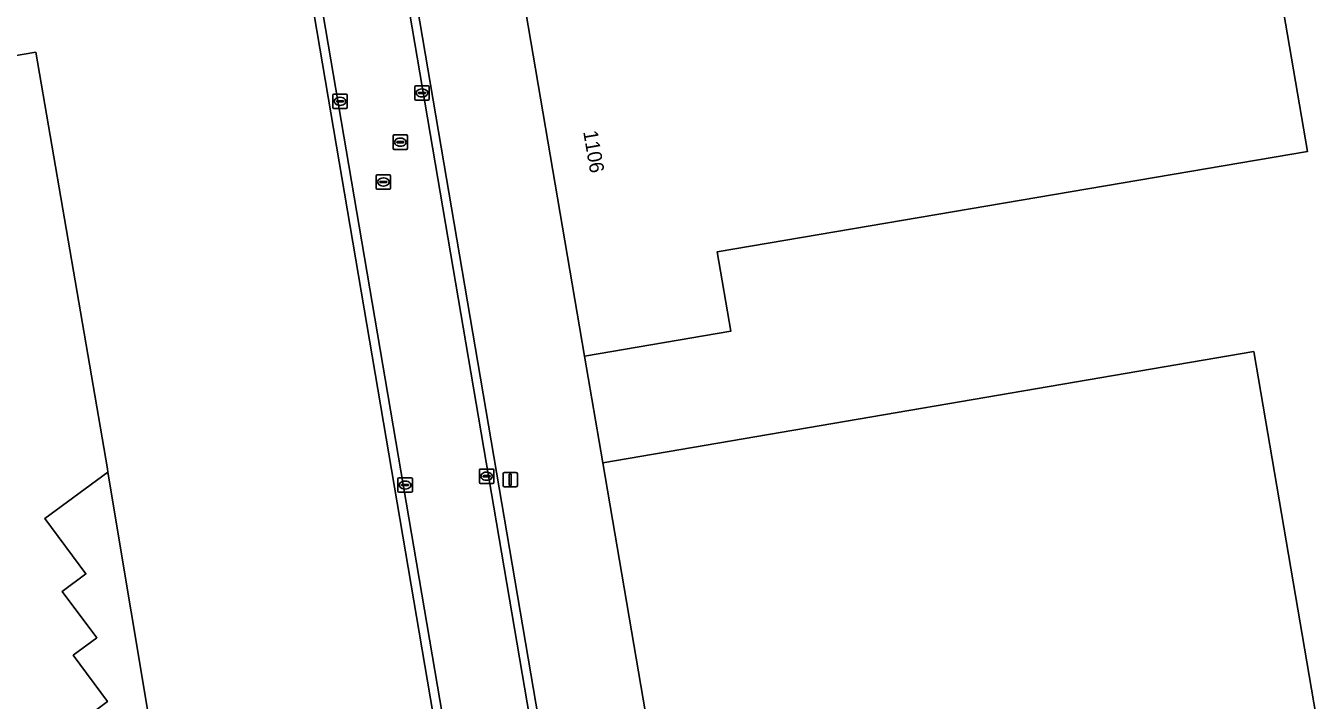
# Model space of a CAD drawing. Extents: x 154324 to 155744, y 382937 to 384188.
# Drawn here: x 154922.2 to 155011.6, y 383247.7 to 383294.5 of the extents above; entities that cross this region are included whole.
import ezdxf

# ---------------------------------------------------------------- set-up
doc = ezdxf.new("R2010")
doc.units = 0
for name, color, linetype in [('IMGEO_Erf', 7, 'Continuous'), ('IMGEO_Kolk', 7, 'Continuous'), ('IMGEO_Lichtmast', 7, 'Continuous'), ('IMGEO_Pand', 7, 'Continuous'), ('IMGEO_Pand_nummerreeks', 7, 'Continuous'), ('IMGEO_Pand_overbouw', 7, 'Continuous'), ('IMGEO_Parkeervlak_open', 7, 'Continuous'), ('IMGEO_Rijbaan_lokaal_gesloten', 7, 'Continuous'), ('IMGEO_Rijbaan_lokaal_open', 7, 'Continuous'), ('IMGEO_Rioolput', 7, 'Continuous')]:
    doc.layers.add(name, color=color, linetype=linetype)

msp = doc.modelspace()

# ---------------------------------------------------------------- linework, layer by layer
at = {"layer": 'IMGEO_Erf'}
for points in [[(154957.636, 383205.007), (154955.126, 383219.621), (154933.063, 383349.385), (154931.446, 383358.867), (154880.326, 383658.587)], [(155062.526, 383340.029), (155003.646, 383330.283), (155005.673, 383318.494), (154961.037, 383310.872), (154960.776, 383312.399), (154955.689, 383311.55), (154954.834, 383316.483), (154953.74, 383316.294), (154953.892, 383315.524), (154953.555, 383315.462), (154954.479, 383309.839), (154956.449, 383298.428), (154958.963, 383298.857), (154958.072, 383304.074), (155006.663, 383312.344), (155011.213, 383285.747), (154970.24, 383278.793), (154971.18, 383273.272), (154961.04, 383271.548), (154962.295, 383264.145), (155007.491, 383271.866), (155014.059, 383233.409)], [(154854.938, 383281.039), (154922.938, 383292.639), (154927.907, 383263.724), (154927.942, 383263.507), (154923.572, 383260.288), (154926.413, 383256.439), (154924.778, 383255.22), (154927.17, 383252.008), (154925.538, 383250.794), (154927.916, 383247.585), (154926.283, 383246.367), (154929.131, 383242.58), (154931.183, 383244.108), (154931.296, 383243.969), (154938.169, 383203.279), (154923.048, 383200.725), (154925.906, 383183.809), (154890.471, 383163.81)]]:
    msp.add_lwpolyline(points, dxfattribs=at)
at = {"layer": 'IMGEO_Kolk'}
for p, q in [((154949.247, 383289.386), (154949.247, 383290.238)), ((154949.322, 383290.312), (154950.174, 383290.312)), ((154949.735, 383290.092), (154949.76, 383290.092)), ((154950.248, 383290.238), (154950.248, 383289.386)), ((154943.56, 383288.804), (154943.56, 383289.656)), ((154943.635, 383289.73), (154944.487, 383289.73)), ((154943.819, 383289.224), (154943.819, 383289.236)), ((154944.257, 383289.187), (154943.859, 383289.187)), ((154943.862, 383289.273), (154944.26, 383289.273)), ((154944.048, 383289.51), (154944.073, 383289.51)), ((154944.303, 383289.236), (154944.303, 383289.224)), ((154944.561, 383289.656), (154944.561, 383288.804)), ((154950.174, 383289.312), (154949.322, 383289.312)), ((154949.506, 383289.806), (154949.506, 383289.818)), ((154949.944, 383289.769), (154949.546, 383289.769)), ((154949.549, 383289.855), (154949.947, 383289.855)), ((154949.758, 383289.532), (154949.733, 383289.532)), ((154949.99, 383289.818), (154949.99, 383289.806)), ((154944.487, 383288.73), (154943.635, 383288.73)), ((154944.071, 383288.95), (154944.046, 383288.95)), ((154948.153, 383263.106), (154949.005, 383263.106)), ((154953.734, 383262.792), (154953.734, 383263.644)), ((154953.809, 383263.718), (154954.661, 383263.718)), ((154953.993, 383263.212), (154953.993, 383263.224)), ((154954.431, 383263.175), (154954.033, 383263.175)), ((154954.036, 383263.261), (154954.434, 383263.261)), ((154954.222, 383263.498), (154954.247, 383263.498)), ((154954.477, 383263.224), (154954.477, 383263.212)), ((154954.735, 383263.644), (154954.735, 383262.792)), ((154948.078, 383262.18), (154948.078, 383263.032)), ((154948.337, 383262.6), (154948.337, 383262.612)), ((154948.775, 383262.563), (154948.377, 383262.563)), ((154948.38, 383262.649), (154948.778, 383262.649)), ((154948.589, 383262.326), (154948.564, 383262.326)), ((154948.566, 383262.886), (154948.591, 383262.886)), ((154948.821, 383262.612), (154948.821, 383262.6)), ((154949.079, 383263.032), (154949.079, 383262.18)), ((154954.661, 383262.718), (154953.809, 383262.718)), ((154954.245, 383262.938), (154954.22, 383262.938)), ((154949.005, 383262.106), (154948.153, 383262.106))]:
    msp.add_line(p, q, dxfattribs=at)
for points in [[(154949.247, 383289.386), (154949.247, 383290.238)], [(154949.322, 383290.312), (154950.174, 383290.312)], [(154950.248, 383290.238), (154950.248, 383289.386)], [(154943.56, 383288.804), (154943.56, 383289.656)], [(154943.635, 383289.73), (154944.487, 383289.73)], [(154944.561, 383289.656), (154944.561, 383288.804)], [(154950.174, 383289.312), (154949.322, 383289.312)], [(154944.487, 383288.73), (154943.635, 383288.73)], [(154948.153, 383263.106), (154949.005, 383263.106)], [(154953.734, 383262.792), (154953.734, 383263.644)], [(154953.809, 383263.718), (154954.661, 383263.718)], [(154954.735, 383263.644), (154954.735, 383262.792)], [(154948.078, 383262.18), (154948.078, 383263.032)], [(154949.079, 383263.032), (154949.079, 383262.18)], [(154954.661, 383262.718), (154953.809, 383262.718)], [(154949.005, 383262.106), (154948.153, 383262.106)]]:
    msp.add_lwpolyline(points, dxfattribs=at)
for centre, radius, start, end in [((154949.324, 383290.236), 0.0765, 91.55205, 178.44795), ((154949.324, 383290.236), 0.0765, 91.55205, 178.44795), ((154950.172, 383290.236), 0.0765, 1.55205, 88.44795), ((154950.172, 383290.236), 0.0765, 1.55205, 88.44795), ((154943.637, 383289.654), 0.0765, 91.55205, 178.44795), ((154943.637, 383289.654), 0.0765, 91.55205, 178.44795), ((154943.859, 383289.233), 0.0403, 85.87752, 175.75265), ((154943.856, 383289.223), 0.0366, 178.93798, 274.71019), ((154944.26, 383289.23), 0.043, 264.86636, 352.45326), ((154944.264, 383289.235), 0.0386, 1.73085, 96.63898), ((154944.485, 383289.654), 0.0765, 1.55205, 88.44795), ((154944.485, 383289.654), 0.0765, 1.55205, 88.44795), ((154949.324, 383289.388), 0.0765, 181.55205, 268.44795), ((154949.324, 383289.388), 0.0765, 181.55205, 268.44795), ((154949.546, 383289.815), 0.0403, 85.87752, 175.75265), ((154949.543, 383289.805), 0.0366, 178.93798, 274.71019), ((154949.947, 383289.812), 0.043, 264.86636, 352.45326), ((154949.951, 383289.817), 0.0386, 1.73085, 96.63898), ((154950.172, 383289.388), 0.0765, 271.55205, 358.44795), ((154950.172, 383289.388), 0.0765, 271.55205, 358.44795), ((154943.637, 383288.806), 0.0765, 181.55205, 268.44795), ((154943.637, 383288.806), 0.0765, 181.55205, 268.44795), ((154944.485, 383288.806), 0.0765, 271.55205, 358.44795), ((154944.485, 383288.806), 0.0765, 271.55205, 358.44795), ((154948.155, 383263.03), 0.0765, 91.55205, 178.44795), ((154948.155, 383263.03), 0.0765, 91.55205, 178.44795), ((154949.003, 383263.03), 0.0765, 1.55205, 88.44795), ((154949.003, 383263.03), 0.0765, 1.55205, 88.44795), ((154953.811, 383263.642), 0.0765, 91.55205, 178.44795), ((154953.811, 383263.642), 0.0765, 91.55205, 178.44795), ((154954.033, 383263.221), 0.0403, 85.87752, 175.75265), ((154954.03, 383263.211), 0.0366, 178.93798, 274.71019), ((154954.434, 383263.218), 0.043, 264.86636, 352.45326), ((154954.438, 383263.223), 0.0386, 1.73085, 96.63898), ((154954.659, 383263.642), 0.0765, 1.55205, 88.44795), ((154954.659, 383263.642), 0.0765, 1.55205, 88.44795), ((154948.155, 383262.182), 0.0765, 181.55205, 268.44795), ((154948.155, 383262.182), 0.0765, 181.55205, 268.44795), ((154948.377, 383262.609), 0.0403, 85.87752, 175.75265), ((154948.374, 383262.599), 0.0366, 178.93798, 274.71019), ((154948.778, 383262.606), 0.043, 264.86636, 352.45326), ((154948.782, 383262.611), 0.0386, 1.73085, 96.63898), ((154949.003, 383262.182), 0.0765, 271.55205, 358.44795), ((154949.003, 383262.182), 0.0765, 271.55205, 358.44795), ((154953.811, 383262.794), 0.0765, 181.55205, 268.44795), ((154953.811, 383262.794), 0.0765, 181.55205, 268.44795), ((154954.659, 383262.794), 0.0765, 271.55205, 358.44795), ((154954.659, 383262.794), 0.0765, 271.55205, 358.44795)]:
    msp.add_arc(centre, radius, start, end, dxfattribs=at)
for centre, major_axis, ratio, start_param, end_param in [((154949.734, 383289.812), (-0.387, 0.002), 0.722429, 4.712389, 7.853982), ((154949.759, 383289.812), (-0.39, 0.002), 0.717154, 1.570796, 4.712389), ((154944.047, 383289.23), (-0.387, 0.002), 0.722429, 4.712389, 7.853982), ((154944.072, 383289.23), (-0.39, 0.002), 0.717154, 1.570796, 4.712389), ((154954.221, 383263.218), (-0.387, 0.002), 0.722429, 4.712389, 7.853982), ((154954.246, 383263.218), (-0.39, 0.002), 0.717154, 1.570796, 4.712389), ((154948.565, 383262.606), (-0.387, 0.002), 0.722429, 4.712389, 7.853982), ((154948.59, 383262.606), (-0.39, 0.002), 0.717154, 1.570796, 4.712389)]:
    msp.add_ellipse(centre, major_axis=major_axis, ratio=ratio, start_param=start_param, end_param=end_param, dxfattribs=at)
at = {"layer": 'IMGEO_Lichtmast'}
for p, q in [((154955.378, 383262.577), (154955.378, 383263.377)), ((154955.378, 383263.377), (154955.378, 383262.577)), ((154955.478, 383263.477), (154956.268, 383263.477)), ((154956.268, 383263.477), (154955.478, 383263.477)), ((154956.368, 383263.377), (154956.368, 383262.577)), ((154956.368, 383262.577), (154956.368, 383263.377)), ((154956.268, 383262.477), (154955.478, 383262.477)), ((154955.478, 383262.477), (154956.268, 383262.477))]:
    msp.add_line(p, q, dxfattribs=at)
msp.add_lwpolyline([(154955.798, 383263.352), (154955.948, 383263.352), (154955.948, 383262.602), (154955.798, 383262.602), (154955.798, 383263.352)], dxfattribs=at)
for centre, start, end in [((154955.478, 383263.377), 90, 180), ((154955.478, 383263.377), 90, 180), ((154956.268, 383263.377), 0, 90), ((154956.268, 383263.377), 360, 90), ((154955.478, 383262.577), 180, 270), ((154955.478, 383262.577), 180, 270), ((154956.268, 383262.577), 270, 0), ((154956.268, 383262.577), 270, 0)]:
    msp.add_arc(centre, 0.1, start, end, dxfattribs=at)
at = {"layer": 'IMGEO_Pand'}
msp.add_lwpolyline([(154958.072, 383304.074), (154958.963, 383298.857), (154956.449, 383298.428), (154961.04, 383271.548), (154971.18, 383273.272), (154970.24, 383278.793), (155011.213, 383285.747), (155006.663, 383312.344)], close=True, dxfattribs=at)
for points in [[(154890.471, 383163.81), (154925.906, 383183.809), (154923.048, 383200.725), (154938.169, 383203.279), (154931.296, 383243.969), (154931.183, 383244.108), (154929.131, 383242.58), (154926.283, 383246.367), (154927.916, 383247.585), (154925.538, 383250.794), (154927.17, 383252.008), (154924.778, 383255.22), (154926.413, 383256.439), (154923.572, 383260.288), (154927.942, 383263.507), (154927.907, 383263.724), (154922.938, 383292.639), (154854.938, 383281.039)], [(154979.95, 383215.582), (154981.386, 383216.111), (154981.866, 383215.269), (155014.059, 383233.409), (155007.491, 383271.866), (154962.295, 383264.145), (154969.397, 383222.533), (154970.312, 383222.697), (154970.556, 383221.2)]]:
    msp.add_lwpolyline(points, dxfattribs=at)
at = {"layer": 'IMGEO_Pand_overbouw'}
msp.add_lwpolyline([(154931.183, 383244.108), (154927.942, 383263.507), (154923.572, 383260.288), (154926.413, 383256.439), (154924.778, 383255.22), (154927.17, 383252.008), (154925.538, 383250.794), (154927.916, 383247.585), (154926.283, 383246.367), (154929.131, 383242.58)], close=True, dxfattribs=at)
at = {"layer": 'IMGEO_Parkeervlak_open'}
msp.add_lwpolyline([(154970.556, 383221.2), (154970.312, 383222.697), (154969.397, 383222.533), (154962.295, 383264.145), (154961.04, 383271.548), (154956.449, 383298.428), (154954.479, 383309.839), (154953.555, 383315.462), (154952.604, 383321.047), (154948.75, 383343.779), (154944.993, 383365.869), (154944.925, 383366.268), (154965.468, 383369.782), (154964.539, 383375.316), (154941.3, 383371.33), (154939.601, 383371.039), (154936.699, 383370.542), (154936.71, 383370.477), (154937.698, 383364.674), (154938.491, 383360.02), (154942.478, 383336.616), (154962.428, 383219.494)], dxfattribs=at)
at = {"layer": 'IMGEO_Rijbaan_lokaal_gesloten'}
for points in [[(154854.425, 383814.31), (154854.653, 383812.991), (154854.813, 383812.024), (154858.483, 383790.497), (154869.559, 383725.258), (154869.596, 383725.133), (154932.04, 383358.964), (154933.662, 383349.45), (154956.051, 383217.962), (154957.681, 383208.024), (154958.22, 383204.737)], [(154961.836, 383219.4), (154937.891, 383359.922), (154875.734, 383724.688)]]:
    msp.add_lwpolyline(points, dxfattribs=at)
at = {"layer": 'IMGEO_Rijbaan_lokaal_open'}
for points in [[(154938.491, 383360.02), (154937.891, 383359.922), (154961.836, 383219.4)], [(154962.428, 383219.494), (154942.478, 383336.616), (154938.491, 383360.02)], [(154958.22, 383204.737), (154957.681, 383208.024), (154956.051, 383217.962), (154933.662, 383349.45), (154932.04, 383358.964), (154931.446, 383358.867), (154933.063, 383349.385), (154955.126, 383219.621), (154957.636, 383205.007)]]:
    msp.add_lwpolyline(points, dxfattribs=at)
at = {"layer": 'IMGEO_Rioolput'}
for p, q in [((154947.746, 383285.971), (154947.746, 383286.823)), ((154947.821, 383286.897), (154948.673, 383286.897)), ((154948.005, 383286.391), (154948.005, 383286.403)), ((154948.443, 383286.354), (154948.045, 383286.354)), ((154948.048, 383286.44), (154948.446, 383286.44)), ((154948.234, 383286.677), (154948.259, 383286.677)), ((154948.489, 383286.403), (154948.489, 383286.391)), ((154948.747, 383286.823), (154948.747, 383285.971)), ((154948.673, 383285.897), (154947.821, 383285.897)), ((154948.257, 383286.117), (154948.232, 383286.117)), ((154946.567, 383283.209), (154946.567, 383284.061)), ((154946.642, 383284.135), (154947.494, 383284.135)), ((154946.826, 383283.629), (154946.826, 383283.641)), ((154946.869, 383283.678), (154947.267, 383283.678)), ((154947.055, 383283.915), (154947.08, 383283.915)), ((154947.31, 383283.641), (154947.31, 383283.629)), ((154947.568, 383284.061), (154947.568, 383283.209)), ((154947.494, 383283.135), (154946.642, 383283.135)), ((154947.264, 383283.592), (154946.866, 383283.592)), ((154947.078, 383283.355), (154947.053, 383283.355))]:
    msp.add_line(p, q, dxfattribs=at)
for points in [[(154947.746, 383285.971), (154947.746, 383286.823)], [(154947.821, 383286.897), (154948.673, 383286.897)], [(154948.747, 383286.823), (154948.747, 383285.971)], [(154948.673, 383285.897), (154947.821, 383285.897)], [(154946.567, 383283.209), (154946.567, 383284.061)], [(154946.642, 383284.135), (154947.494, 383284.135)], [(154947.568, 383284.061), (154947.568, 383283.209)], [(154947.494, 383283.135), (154946.642, 383283.135)]]:
    msp.add_lwpolyline(points, dxfattribs=at)
for centre, radius, start, end in [((154947.823, 383286.821), 0.0765, 91.55205, 178.44795), ((154947.823, 383286.821), 0.0765, 91.55205, 178.44795), ((154948.045, 383286.4), 0.0403, 85.87752, 175.75265), ((154948.042, 383286.39), 0.0366, 178.93798, 274.71019), ((154948.446, 383286.397), 0.043, 264.86636, 352.45326), ((154948.45, 383286.402), 0.0386, 1.73085, 96.63898), ((154948.671, 383286.821), 0.0765, 1.55205, 88.44795), ((154948.671, 383286.821), 0.0765, 1.55205, 88.44795), ((154947.823, 383285.973), 0.0765, 181.55205, 268.44795), ((154947.823, 383285.973), 0.0765, 181.55205, 268.44795), ((154948.671, 383285.973), 0.0765, 271.55205, 358.44795), ((154948.671, 383285.973), 0.0765, 271.55205, 358.44795), ((154946.644, 383284.059), 0.0765, 91.55205, 178.44795), ((154946.644, 383284.059), 0.0765, 91.55205, 178.44795), ((154946.866, 383283.638), 0.0403, 85.87752, 175.75265), ((154946.863, 383283.628), 0.0366, 178.93798, 274.71019), ((154947.267, 383283.635), 0.043, 264.86636, 352.45326), ((154947.271, 383283.64), 0.0386, 1.73085, 96.63898), ((154947.492, 383284.059), 0.0765, 1.55205, 88.44795), ((154947.492, 383284.059), 0.0765, 1.55205, 88.44795), ((154946.644, 383283.211), 0.0765, 181.55205, 268.44795), ((154946.644, 383283.211), 0.0765, 181.55205, 268.44795), ((154947.492, 383283.211), 0.0765, 271.55205, 358.44795), ((154947.492, 383283.211), 0.0765, 271.55205, 358.44795)]:
    msp.add_arc(centre, radius, start, end, dxfattribs=at)
for centre, major_axis, ratio, start_param, end_param in [((154948.233, 383286.397), (-0.387, 0.002), 0.722429, 4.712389, 7.853982), ((154948.258, 383286.397), (-0.39, 0.002), 0.717154, 1.570796, 4.712389), ((154947.054, 383283.635), (-0.387, 0.002), 0.722429, 4.712389, 7.853982), ((154947.079, 383283.635), (-0.39, 0.002), 0.717154, 1.570796, 4.712389)]:
    msp.add_ellipse(centre, major_axis=major_axis, ratio=ratio, start_param=start_param, end_param=end_param, dxfattribs=at)

# ---------------------------------------------------------------- texts
at = {"layer": 'IMGEO_Pand_nummerreeks'}
msp.add_text('1106', height=1, rotation=279.69162, dxfattribs=at).set_placement((154960.935, 383287.131))

doc.saveas('drawing.dxf')
